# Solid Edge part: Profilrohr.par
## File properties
Username: bmolnar
Dokumentum tartalom típus: 0
Author: bmolnar
Last saved by: bmolnar
Revision: 79
Sűrűség: 0,000 kg/m^3
Pontosság: 0,990
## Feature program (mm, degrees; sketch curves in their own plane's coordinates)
base feature "unnamed BaseFeature 1"
thread "unnamed Thread 1"
thread "Menet_2"  ThreadDepth = 6 mm
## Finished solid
Body 1: solid body, 153 faces, 364 edges, 236 vertices.
  Faces by surface: plane 74, cylinder 65, cone 10, torus 4
  Edges by curve: line 220, circle 140, curve on surface 2, spline 2
Bounding box of the edges (mm; curved faces can reach further): 46.000 x 51.000 x 54.500, from (-23, -24, 0) to (23, 27, 54.5).
Cylindrical faces by radius (mm): R0.3 x24, R0.8 x2, R2.9 x8, R4.283 x4, R4.4 x16, R16 x1, R16.85 x2, R17.05 x2, R17.9 x2, R30 x4
Conical faces (half-angle, radius in mm at the cone's reference point): 21 deg R16.325 x2, 45 deg R4.783 x2, 45 deg R17.1 x2, 45 deg R17.15 x2, 45 deg R17.2 x2
Toroidal faces (ring radius, tube radius in mm): R17.7 r0.2 x4
Planar faces by outward normal: +x 6, +y 9, +z 8, -x 6, -y 5, -z 8, oblique 32
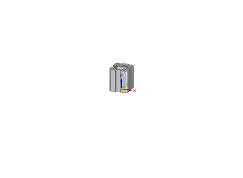
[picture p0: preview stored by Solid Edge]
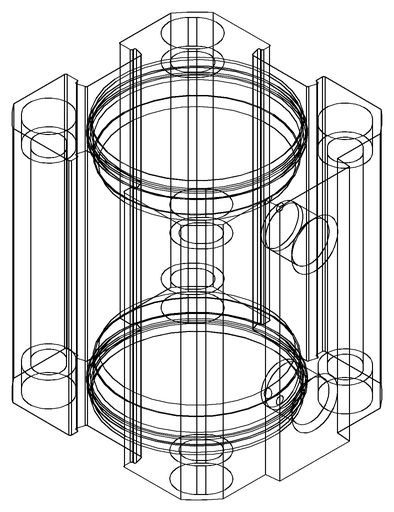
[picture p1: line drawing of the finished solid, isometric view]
